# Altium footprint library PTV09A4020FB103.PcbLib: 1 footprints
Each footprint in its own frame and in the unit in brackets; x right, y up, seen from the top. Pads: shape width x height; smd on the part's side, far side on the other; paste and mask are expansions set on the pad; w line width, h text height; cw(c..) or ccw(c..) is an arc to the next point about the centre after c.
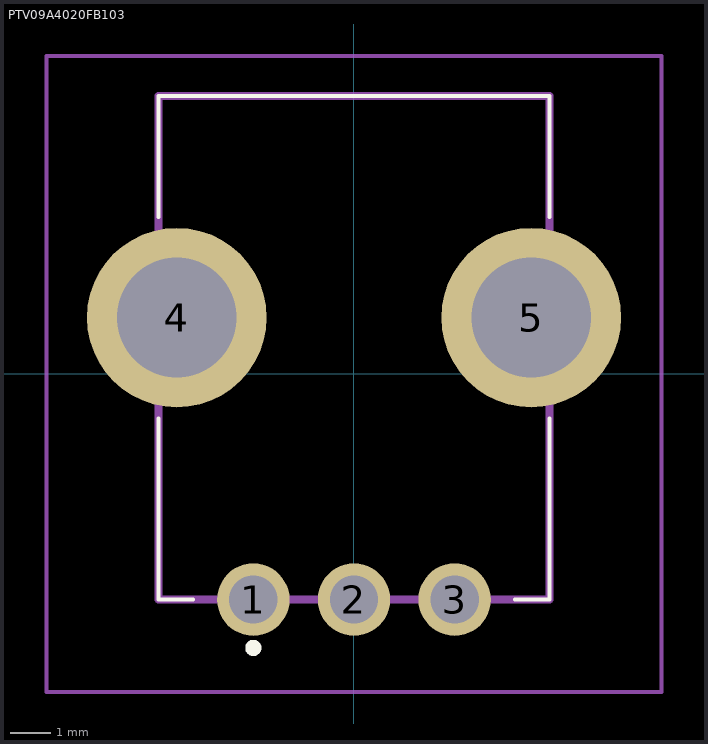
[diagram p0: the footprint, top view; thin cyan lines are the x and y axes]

## PTV09A4020FB103 [mm]
pads (5):
  round 1.8 hole 1.2: 1(-2.5,-5.6) 2(0,-5.6) 3(2.5,-5.6)
  round 4.46 hole 2.973: 4(-4.4,1.4) 5(4.4,1.4)
Top Overlay:
  lines w0.1: -4.85,-1.1 -4.85,-5.6 -4,-5.6 ; -4.85,3.9 -4.85,6.9 4.85,6.9 4.85,3.9 ; 4,-5.6 4.85,-5.6 4.85,-1.1
  lines w0.2: -2.6,-6.8 -2.6,-6.8 ; -2.6,-6.8 cw(c-2.5,-6.8) -2.4,-6.8 ; -2.6,-6.8 ccw(c-2.5,-6.8) -2.4,-6.8 ; -2.4,-6.8 -2.4,-6.8
Mechanical 15:
  lines w0.2: -4.85,-5.6 4.85,-5.6 4.85,6.9 -4.85,6.9 -4.85,-5.6
Mechanical 20:
  lines w0.1: -7.63,-7.9 7.63,-7.9 7.63,7.9 -7.63,7.9 -7.63,-7.9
